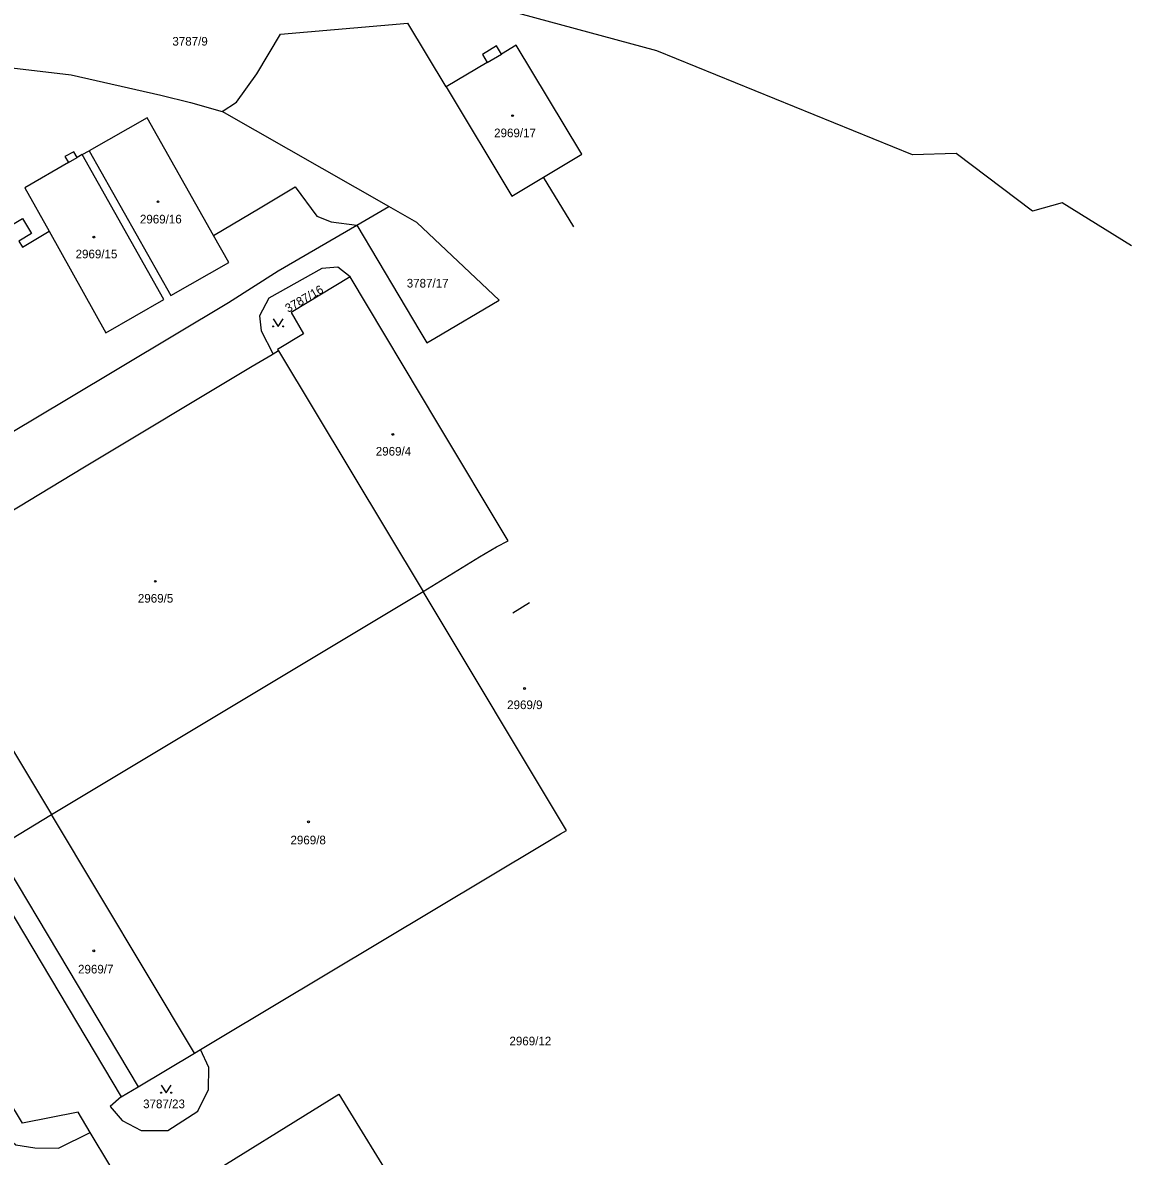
# Model space of a CAD drawing. Extents: x -527335 to -526256, y -1079142 to -1077809.
# Drawn here: x -526473.7 to -526255.8, y -1078664.8 to -1078442 of the extents above; entities that cross this region are included whole.
import ezdxf

# ---------------------------------------------------------------- set-up
doc = ezdxf.new("R2010")
doc.units = 0
for name, color, linetype in [('Vrstva 1', 7, 'Continuous'), ('Vrstva 2', 7, 'Continuous'), ('Vrstva 3', 7, 'Continuous'), ('Vrstva 4', 7, 'Continuous'), ('Vrstva 5', 7, 'Continuous')]:
    doc.layers.add(name, color=color, linetype=linetype)

msp = doc.modelspace()

# ---------------------------------------------------------------- linework, layer by layer
at = {"layer": 'Vrstva 1'}
for p, q in [((-526390.49, -1078454.67), (-526398.01, -1078442.14)), ((-526401.75, -1078478.18), (-526434.53, -1078459.51)), ((-526462.04, -1078467.96), (-526460.66, -1078467.18)), ((-526365.44, -1078482.13), (-526371.4, -1078472.38)), ((-526408.05, -1078481.83), (-526401.75, -1078478.18)), ((-526423.48, -1078506.53), (-526424.51, -1078507.15)), ((-526423.48, -1078506.53), (-526395.01, -1078553.82)), ((-526496.51, -1078550.45), (-526468.06, -1078597.62)), ((-526468.06, -1078597.62), (-526395.01, -1078553.82)), ((-526366.88, -1078600.75), (-526395.01, -1078553.82)), ((-526439.96, -1078644.47), (-526468.06, -1078597.62)), ((-526482.37, -1078606.2), (-526454.36, -1078653.08)), ((-526439.96, -1078644.47), (-526438.79, -1078643.77)), ((-526456.6, -1078666.52), (-526460.45, -1078660.06))]:
    msp.add_line(p, q, dxfattribs=at)
for points in [[(-526255.84, -1078485.88), (-526269.44, -1078477.46), (-526275.29, -1078479.08), (-526290.24, -1078467.75), (-526298.87, -1078468), (-526349.1, -1078447.58), (-526381.09, -1078438.93), (-526412.01, -1078434.75), (-526470.91, -1078435.12), (-526515.41, -1078439.88), (-526541.88, -1078447.21), (-526576.22, -1078459.13), (-526589.61, -1078459.9), (-526628.8, -1078481.46), (-526632.26, -1078483.8)], [(-526434.53, -1078459.51), (-526431.72, -1078457.68), (-526427.71, -1078452.11), (-526423.05, -1078444.29), (-526398.01, -1078442.14)], [(-526364.05, -1078467.53), (-526376.73, -1078446.46), (-526379.64, -1078448.2), (-526380.59, -1078446.61), (-526383.37, -1078448.26), (-526382.42, -1078449.85), (-526390.49, -1078454.67)], [(-526561.62, -1078458.12), (-526556.1, -1078456.24), (-526538.7, -1078451.42), (-526526.69, -1078449.93), (-526506.02, -1078449.43), (-526490.82, -1078449.67), (-526475.86, -1078450.92), (-526464.21, -1078452.25), (-526446.58, -1078456.25), (-526440.77, -1078457.7), (-526434.53, -1078459.51)], [(-526390.49, -1078454.67), (-526377.62, -1078476.11), (-526371.4, -1078472.38)], [(-526436.22, -1078483.83), (-526449.28, -1078460.76), (-526460.66, -1078467.18)], [(-526462.04, -1078467.96), (-526463.04, -1078468.53), (-526463.67, -1078467.44), (-526465.44, -1078468.33), (-526464.75, -1078469.52), (-526473.35, -1078474.48), (-526468.56, -1078483.02)], [(-526468.56, -1078483.02), (-526457.39, -1078502.95), (-526445.99, -1078496.44), (-526462.04, -1078467.96)], [(-526460.66, -1078467.18), (-526444.61, -1078495.62), (-526433.22, -1078489.14), (-526436.22, -1078483.83)], [(-526371.4, -1078472.38), (-526363.86, -1078467.85), (-526364.05, -1078467.53)], [(-526436.22, -1078483.83), (-526427.06, -1078478.38), (-526420.17, -1078474.28), (-526415.95, -1078480.07), (-526413.09, -1078481.16), (-526408.05, -1078481.83)], [(-526489.6, -1078482.49), (-526479.94, -1078477.61), (-526477.03, -1078482.5), (-526473.76, -1078480.51), (-526472, -1078483.43), (-526474.52, -1078484.96), (-526473.8, -1078486.15), (-526468.56, -1078483.02)], [(-526380.11, -1078496.53), (-526396.29, -1078481.29), (-526401.75, -1078478.18)], [(-526523.77, -1078550.34), (-526505.2, -1078540.05), (-526486.35, -1078528.69), (-526465.12, -1078516.06), (-526433.26, -1078496.98), (-526423.51, -1078490.78), (-526408.05, -1078481.83)], [(-526408.05, -1078481.83), (-526395.67, -1078502.64), (-526394.31, -1078504.92)], [(-526409.39, -1078491.99), (-526411.77, -1078490.06), (-526414.97, -1078490.36), (-526425.38, -1078496.15), (-526427.22, -1078499.62), (-526426.89, -1078502.56), (-526424.57, -1078507.03), (-526424.51, -1078507.15)], [(-526409.39, -1078491.99), (-526420.96, -1078499), (-526418.53, -1078503.14), (-526423.65, -1078506.24), (-526423.48, -1078506.53)], [(-526380.64, -1078545.01), (-526378.32, -1078543.81), (-526392.13, -1078520.81), (-526409.39, -1078491.99)], [(-526394.31, -1078504.92), (-526392.74, -1078503.99), (-526380.11, -1078496.53)], [(-526424.51, -1078507.15), (-526424.73, -1078507.28), (-526428.61, -1078509.6), (-526461.89, -1078529.55), (-526491.29, -1078547.29), (-526495.23, -1078549.67), (-526495.49, -1078549.83)], [(-526395.01, -1078553.82), (-526383.96, -1078547.01), (-526380.64, -1078545.01)], [(-526507.8, -1078581.45), (-526513.68, -1078580.21), (-526515.08, -1078581.28), (-526517.57, -1078586.65), (-526517.96, -1078593.09), (-526516.49, -1078609.57), (-526490.68, -1078647.6), (-526486.57, -1078649.86), (-526481.38, -1078657.09), (-526475.07, -1078662.48), (-526471.37, -1078663.11), (-526466.68, -1078663.19), (-526460.45, -1078660.06)], [(-526460.45, -1078660.06), (-526462.86, -1078656.06), (-526473.81, -1078658.24), (-526496.71, -1078620.35), (-526488.48, -1078613.73), (-526499.93, -1078594.58), (-526505.29, -1078597.66), (-526511.58, -1078587.21), (-526506.29, -1078583.97), (-526507.8, -1078581.45)], [(-526482.37, -1078606.2), (-526479.05, -1078604.2), (-526468.06, -1078597.62)], [(-526438.79, -1078643.77), (-526435.21, -1078641.63), (-526371.52, -1078603.53), (-526368.01, -1078601.43), (-526366.88, -1078600.75)], [(-526454.36, -1078653.08), (-526456.53, -1078655), (-526454.22, -1078657.74), (-526450.45, -1078659.69), (-526445.2, -1078659.72), (-526439.34, -1078655.88), (-526437.19, -1078651.61), (-526437.18, -1078647.33), (-526438.79, -1078643.77)], [(-526454.36, -1078653.08), (-526451.02, -1078651.08), (-526439.96, -1078644.47)], [(-526443.9, -1078676.11), (-526439.15, -1078673.33), (-526440.79, -1078670.66), (-526411.59, -1078652.55), (-526399.61, -1078672.09), (-526428.92, -1078690.08), (-526430.5, -1078687.59), (-526435.4, -1078690.65)]]:
    msp.add_lwpolyline(points, dxfattribs=at)
at = {"layer": 'Vrstva 3'}
for points in [[(-526424.52, -1078500.2), (-526423.52, -1078501.7), (-526422.52, -1078500.2)], [(-526446.55, -1078650.76), (-526445.55, -1078652.26), (-526444.55, -1078650.76)]]:
    msp.add_lwpolyline(points, dxfattribs=at)
for centre in [(-526424.52, -1078501.7), (-526422.52, -1078501.7), (-526446.55, -1078652.26), (-526444.55, -1078652.26)]:
    msp.add_circle(centre, 0.1, dxfattribs=at)
at = {"layer": 'Vrstva 4'}
for p, q in [((-526382.42, -1078449.85), (-526379.64, -1078448.2)), ((-526464.75, -1078469.52), (-526463.04, -1078468.53)), ((-526377.42, -1078557.96), (-526374.1, -1078555.96)), ((-526479.05, -1078604.2), (-526451.02, -1078651.08))]:
    msp.add_line(p, q, dxfattribs=at)
at = {"layer": 'Vrstva 5'}
for centre in [(-526377.45, -1078460.31), (-526447.14, -1078477.22), (-526459.75, -1078484.16), (-526400.99, -1078522.92), (-526447.67, -1078551.79), (-526375.09, -1078572.85), (-526417.57, -1078599.05), (-526459.77, -1078624.4)]:
    msp.add_circle(centre, 0.175, dxfattribs=at)

# ---------------------------------------------------------------- texts
at = {"layer": 'Vrstva 2'}
for s, p in [('3787/9', (-526444.32, -1078446.54)), ('2969/17', (-526381.08, -1078464.54)), ('2969/16', (-526450.7, -1078481.48)), ('2969/15', (-526463.34, -1078488.33)), ('3787/17', (-526398.26, -1078494.07)), ('2969/4', (-526404.34, -1078527.09)), ('2969/5', (-526451.1, -1078555.98)), ('2969/9', (-526378.52, -1078576.9)), ('2969/8', (-526421.11, -1078603.47)), ('2969/7', (-526462.86, -1078628.84)), ('2969/12', (-526378.07, -1078642.96)), ('3787/23', (-526450.07, -1078655.31))]:
    msp.add_text(s, height=1.7, dxfattribs=at).set_placement(p)
msp.add_text('3787/16', height=1.7, rotation=30, dxfattribs=at).set_placement((-526421.56, -1078499.06))

doc.saveas('drawing.dxf')
